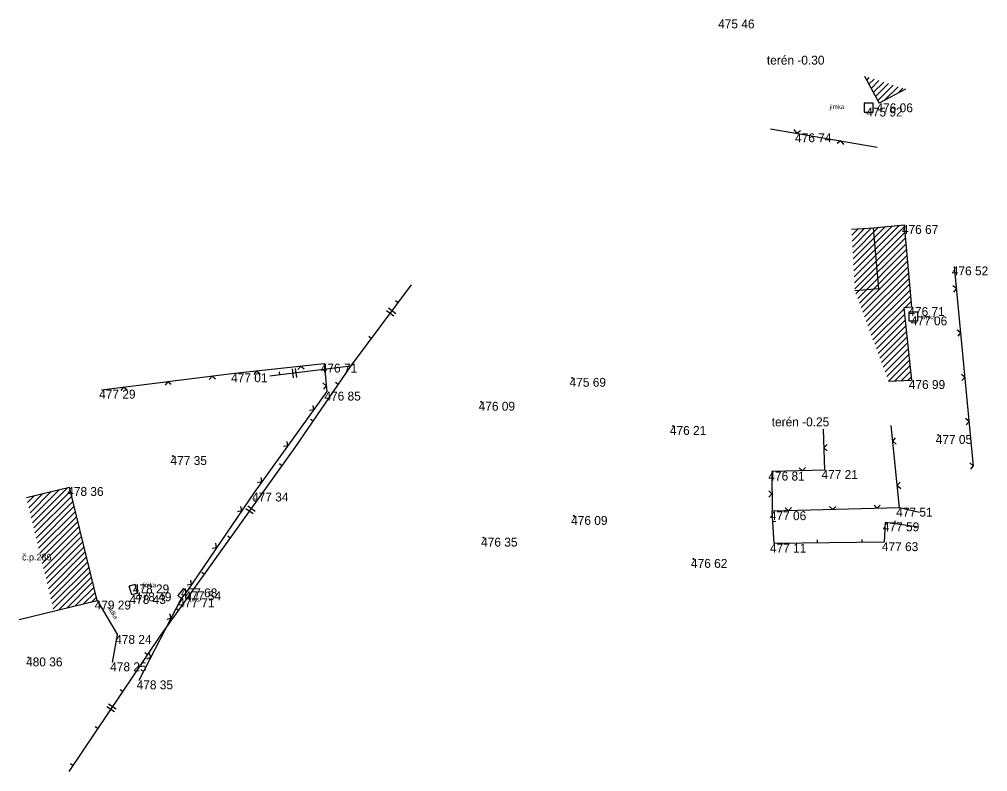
# Model space of a CAD drawing. Extents: x -553731 to -553573, y -1076100 to -1075378.
# Drawn here: x -553694.9 to -553586.1, y -1076100.4 to -1076015.8 of the extents above; entities that cross this region are included whole.
import ezdxf

# ---------------------------------------------------------------- set-up
doc = ezdxf.new("R2010")
doc.units = 0
for name, color, linetype in [('1', 7, 'Continuous'), ('12', 7, 'Continuous'), ('14', 7, 'Continuous'), ('18', 7, 'Continuous'), ('32', 7, 'Continuous'), ('50', 7, 'Continuous'), ('52', 7, 'Continuous'), ('54', 7, 'Continuous'), ('6', 7, 'Continuous'), ('62', 7, 'Continuous')]:
    doc.layers.add(name, color=color, linetype=linetype)

# ---------------------------------------------------------------- blocks, each defined once
blk = doc.blocks.new('POINT_DISPLAY')
blk.add_line((0, 0), (0, 0))
blk = doc.blocks.new('T')
at = {"layer": '6'}
blk.add_circle((0, 0), 0.05, dxfattribs=at)
blk = doc.blocks.new('SA')
at = {"layer": '50'}
blk.add_lwpolyline([(-0.5, -0.5), (0.5, -0.5), (0.5, 0.5), (-0.5, 0.5)], close=True, dxfattribs=at)
blk = doc.blocks.new('ROV')
at = {"layer": '62'}
for p, q in [((-0.348, -0.51), (-0.348, 0.51)), ((0, -0.51), (0, 0.51))]:
    blk.add_line(p, q, dxfattribs=at)

msp = doc.modelspace()

# ---------------------------------------------------------------- linework, layer by layer
at = {"layer": '12'}
for p, q in [((-553610.46, -1076028.1), (-553598.51, -1076030.16)), ((-553607.51, -1076028.61), (-553607.8, -1076028.2)), ((-553607.51, -1076028.61), (-553607.1, -1076028.32)), ((-553602.58, -1076029.46), (-553602.99, -1076029.75)), ((-553602.58, -1076029.46), (-553602.29, -1076029.87)), ((-553589.83, -1076043.58), (-553587.69, -1076066.04)), ((-553589.59, -1076046.07), (-553589.98, -1076045.75)), ((-553589.59, -1076046.07), (-553589.91, -1076046.46)), ((-553589.12, -1076051.05), (-553589.51, -1076050.73)), ((-553589.12, -1076051.05), (-553589.44, -1076051.43)), ((-553670.71, -1076055.59), (-553660.63, -1076054.5)), ((-553663.25, -1076054.78), (-553663.57, -1076055.17)), ((-553663.25, -1076054.78), (-553662.86, -1076055.1)), ((-553660.63, -1076054.5), (-553660.33, -1076057.65)), ((-553685.64, -1076057.43), (-553670.71, -1076055.59)), ((-553673.23, -1076055.9), (-553673.54, -1076056.3)), ((-553673.23, -1076055.9), (-553672.84, -1076056.21)), ((-553668.22, -1076055.32), (-553668.54, -1076055.71)), ((-553668.22, -1076055.32), (-553667.83, -1076055.64)), ((-553588.64, -1076056.02), (-553589.03, -1076055.71)), ((-553588.64, -1076056.02), (-553588.96, -1076056.41)), ((-553683.16, -1076057.12), (-553683.47, -1076057.52)), ((-553683.16, -1076057.12), (-553682.76, -1076057.43)), ((-553678.2, -1076056.51), (-553678.5, -1076056.91)), ((-553678.2, -1076056.51), (-553677.8, -1076056.82)), ((-553660.39, -1076056.99), (-553660.78, -1076056.67)), ((-553660.39, -1076056.99), (-553660.71, -1076057.38)), ((-553660.33, -1076057.65), (-553668.48, -1076068.99)), ((-553661.79, -1076059.68), (-553661.87, -1076059.19)), ((-553661.79, -1076059.68), (-553662.28, -1076059.76)), ((-553588.17, -1076061), (-553588.56, -1076060.68)), ((-553595.98, -1076070.69), (-553596.92, -1076061.46)), ((-553588.17, -1076061), (-553588.49, -1076061.39)), ((-553604.38, -1076066.47), (-553604.54, -1076061.86)), ((-553596.74, -1076063.23), (-553596.42, -1076062.84)), ((-553664.71, -1076063.74), (-553665.2, -1076063.82)), ((-553664.71, -1076063.74), (-553664.79, -1076063.25)), ((-553604.47, -1076063.97), (-553604.12, -1076063.6)), ((-553596.74, -1076063.23), (-553596.35, -1076063.55)), ((-553604.47, -1076063.97), (-553604.1, -1076064.31)), ((-553587.7, -1076065.98), (-553588.08, -1076065.66)), ((-553587.7, -1076065.98), (-553588.02, -1076066.36)), ((-553604.38, -1076066.47), (-553610.34, -1076066.64)), ((-553610.34, -1076066.64), (-553610.28, -1076071.09)), ((-553606.88, -1076066.54), (-553607.24, -1076066.2)), ((-553606.88, -1076066.54), (-553606.54, -1076066.18)), ((-553667.62, -1076067.8), (-553668.12, -1076067.88)), ((-553667.62, -1076067.8), (-553667.71, -1076067.31)), ((-553596.23, -1076068.2), (-553595.92, -1076067.81)), ((-553596.23, -1076068.2), (-553595.84, -1076068.52)), ((-553668.48, -1076068.99), (-553676.05, -1076080.09)), ((-553610.31, -1076069.14), (-553610.67, -1076068.79)), ((-553610.31, -1076069.14), (-553610.66, -1076069.5)), ((-553598.48, -1076070.76), (-553598.84, -1076070.42)), ((-553598.48, -1076070.76), (-553598.14, -1076070.4)), ((-553669.89, -1076071.06), (-553670.38, -1076071.15)), ((-553669.89, -1076071.06), (-553669.98, -1076070.56)), ((-553595.98, -1076070.69), (-553610.28, -1076071.09)), ((-553610.07, -1076074.73), (-553610.28, -1076071.09)), ((-553608.47, -1076071.04), (-553608.84, -1076070.7)), ((-553608.47, -1076071.04), (-553608.13, -1076070.68)), ((-553603.48, -1076070.9), (-553603.84, -1076070.56)), ((-553603.48, -1076070.9), (-553603.13, -1076070.54)), ((-553593.72, -1076071.23), (-553595.98, -1076070.69)), ((-553610.21, -1076072.23), (-553609.86, -1076072.21)), ((-553597.58, -1076072.34), (-553597.69, -1076074.57)), ((-553594.05, -1076072.85), (-553597.58, -1076072.34)), ((-553596.52, -1076072.49), (-553596.47, -1076072.15)), ((-553672.71, -1076075.19), (-553672.8, -1076074.69)), ((-553597.69, -1076074.57), (-553610.07, -1076074.73)), ((-553605.19, -1076074.67), (-553605.19, -1076074.32)), ((-553600.19, -1076074.6), (-553600.19, -1076074.25)), ((-553672.71, -1076075.19), (-553673.2, -1076075.28)), ((-553675.52, -1076079.32), (-553675.62, -1076078.82)), ((-553675.52, -1076079.32), (-553676.02, -1076079.41)), ((-553676.68, -1076080.88), (-553681.44, -1076090.1)), ((-553677.83, -1076083.1), (-553678.3, -1076083.25)), ((-553677.83, -1076083.1), (-553677.98, -1076082.62)), ((-553680.12, -1076087.54), (-553680.6, -1076087.7)), ((-553680.12, -1076087.54), (-553680.27, -1076087.07))]:
    msp.add_line(p, q, dxfattribs=at)
at = {"layer": '14'}
for p, q in [((-553599.92, -1076022.19), (-553598.28, -1076025.25)), ((-553595.29, -1076023.65), (-553598.28, -1076025.25)), ((-553598.92, -1076039.23), (-553595.43, -1076038.92)), ((-553594.61, -1076048.15), (-553595.43, -1076038.92)), ((-553601.38, -1076039.39), (-553598.92, -1076039.23)), ((-553598.31, -1076046.09), (-553598.92, -1076039.23)), ((-553598.31, -1076046.09), (-553601, -1076046.33)), ((-553594.61, -1076048.15), (-553595.48, -1076048.24)), ((-553595.48, -1076048.24), (-553594.64, -1076056.35)), ((-553597.22, -1076056.47), (-553594.64, -1076056.35)), ((-553694.09, -1076069.55), (-553689.23, -1076068.37)), ((-553686.14, -1076081.13), (-553689.23, -1076068.37)), ((-553694.88, -1076083.25), (-553686.14, -1076081.13))]:
    msp.add_line(p, q, dxfattribs=at)
at = {"layer": '18'}
for p, q in [((-553681.86, -1076079.32), (-553682.52, -1076079.51)), ((-553682.25, -1076080.5), (-553682.52, -1076079.51)), ((-553681.59, -1076080.31), (-553681.86, -1076079.32)), ((-553676.45, -1076079.76), (-553677.08, -1076080.55)), ((-553676.05, -1076080.09), (-553676.68, -1076080.88)), ((-553676.45, -1076079.76), (-553676.05, -1076080.09)), ((-553686.14, -1076081.13), (-553683.86, -1076084.99)), ((-553681.59, -1076080.31), (-553682.25, -1076080.5)), ((-553677.08, -1076080.55), (-553676.68, -1076080.88)), ((-553684.41, -1076088.07), (-553683.86, -1076084.99))]:
    msp.add_line(p, q, dxfattribs=at)
at = {"layer": '32'}
for p, q in [((-553599.67, -1076022.66), (-553599.38, -1076022.36)), ((-553599.42, -1076023.11), (-553598.84, -1076022.53)), ((-553599.18, -1076023.58), (-553598.3, -1076022.7)), ((-553598.93, -1076024.04), (-553597.76, -1076022.87)), ((-553598.68, -1076024.5), (-553597.23, -1076023.04)), ((-553598.44, -1076024.96), (-553596.69, -1076023.21)), ((-553597.72, -1076024.95), (-553596.15, -1076023.38)), ((-553596.2, -1076024.14), (-553595.61, -1076023.55)), ((-553601.34, -1076040.06), (-553600.62, -1076039.34)), ((-553601.31, -1076040.73), (-553599.86, -1076039.29)), ((-553601.27, -1076041.4), (-553599.11, -1076039.24)), ((-553601.23, -1076042.07), (-553598.34, -1076039.18)), ((-553601.2, -1076042.74), (-553597.56, -1076039.11)), ((-553601.16, -1076043.41), (-553596.79, -1076039.04)), ((-553601.12, -1076044.08), (-553596.01, -1076038.97)), ((-553601.09, -1076044.76), (-553595.42, -1076039.08)), ((-553601.05, -1076045.43), (-553595.36, -1076039.73)), ((-553601.01, -1076046.1), (-553595.3, -1076040.38)), ((-553600.88, -1076046.67), (-553595.24, -1076041.03)), ((-553600.68, -1076047.18), (-553595.19, -1076041.68)), ((-553600.49, -1076047.7), (-553595.13, -1076042.33)), ((-553600.3, -1076048.21), (-553595.07, -1076042.98)), ((-553600.11, -1076048.73), (-553595.01, -1076043.63)), ((-553599.92, -1076049.24), (-553594.95, -1076044.28)), ((-553599.72, -1076049.76), (-553594.9, -1076044.93)), ((-553599.53, -1076050.27), (-553594.84, -1076045.58)), ((-553599.34, -1076050.79), (-553594.78, -1076046.23)), ((-553599.15, -1076051.3), (-553594.72, -1076046.88)), ((-553595.37, -1076048.23), (-553594.67, -1076047.53)), ((-553598.96, -1076051.82), (-553595.47, -1076048.33)), ((-553598.77, -1076052.33), (-553595.41, -1076048.97)), ((-553598.57, -1076052.85), (-553595.34, -1076049.61)), ((-553598.38, -1076053.36), (-553595.27, -1076050.26)), ((-553598.19, -1076053.88), (-553595.21, -1076050.9)), ((-553598, -1076054.39), (-553595.14, -1076051.54)), ((-553597.81, -1076054.91), (-553595.07, -1076052.18)), ((-553597.61, -1076055.43), (-553595.01, -1076052.82)), ((-553597.42, -1076055.94), (-553594.94, -1076053.46)), ((-553597.23, -1076056.46), (-553594.87, -1076054.1)), ((-553596.5, -1076056.44), (-553594.81, -1076054.74)), ((-553595.76, -1076056.4), (-553594.74, -1076055.38)), ((-553595.02, -1076056.37), (-553594.67, -1076056.02)), ((-553693.95, -1076070.12), (-553693.16, -1076069.32)), ((-553693.81, -1076070.69), (-553692.22, -1076069.09)), ((-553693.68, -1076071.26), (-553691.29, -1076068.87)), ((-553693.54, -1076071.82), (-553690.36, -1076068.64)), ((-553693.4, -1076072.39), (-553689.43, -1076068.42)), ((-553693.26, -1076072.96), (-553689.12, -1076068.82)), ((-553693.12, -1076073.53), (-553688.98, -1076069.39)), ((-553692.99, -1076074.1), (-553688.84, -1076069.96)), ((-553692.85, -1076074.67), (-553688.71, -1076070.53)), ((-553692.71, -1076075.24), (-553688.57, -1076071.1)), ((-553692.57, -1076075.81), (-553688.43, -1076071.67)), ((-553692.44, -1076076.38), (-553688.29, -1076072.24)), ((-553692.3, -1076076.95), (-553688.16, -1076072.81)), ((-553692.16, -1076077.52), (-553688.02, -1076073.38)), ((-553692.02, -1076078.09), (-553687.88, -1076073.94)), ((-553691.88, -1076078.66), (-553687.74, -1076074.51)), ((-553691.75, -1076079.22), (-553687.6, -1076075.08)), ((-553691.61, -1076079.79), (-553687.47, -1076075.65)), ((-553691.47, -1076080.36), (-553687.33, -1076076.22)), ((-553691.33, -1076080.93), (-553687.19, -1076076.79)), ((-553691.2, -1076081.5), (-553687.05, -1076077.36)), ((-553691.06, -1076082.07), (-553686.92, -1076077.93)), ((-553690.45, -1076082.18), (-553686.78, -1076078.5)), ((-553689.52, -1076081.95), (-553686.64, -1076079.07)), ((-553688.59, -1076081.72), (-553686.5, -1076079.64)), ((-553687.66, -1076081.5), (-553686.36, -1076080.21)), ((-553686.72, -1076081.27), (-553686.23, -1076080.78))]:
    msp.add_line(p, q, dxfattribs=at)
at = {"layer": '62'}
for p, q in [((-553650.84, -1076045.65), (-553657.65, -1076054.77)), ((-553652.34, -1076047.65), (-553652.62, -1076047.44)), ((-553655.33, -1076051.66), (-553655.61, -1076051.45)), ((-553657.65, -1076054.77), (-553666.73, -1076055.91)), ((-553657.65, -1076054.77), (-553663.91, -1076063.94)), ((-553660.63, -1076055.14), (-553660.58, -1076055.49)), ((-553665.59, -1076055.77), (-553665.63, -1076055.42)), ((-553659.06, -1076056.83), (-553659.35, -1076056.64)), ((-553661.88, -1076060.96), (-553662.17, -1076060.77)), ((-553663.91, -1076063.94), (-553679.09, -1076085.13)), ((-553665.37, -1076065.97), (-553665.65, -1076065.77)), ((-553668.28, -1076070.04), (-553668.56, -1076069.83)), ((-553671.19, -1076074.1), (-553671.47, -1076073.9)), ((-553674.1, -1076078.17), (-553674.39, -1076077.96)), ((-553677.01, -1076082.23), (-553677.3, -1076082.03)), ((-553679.09, -1076085.13), (-553689.31, -1076100.35)), ((-553680.48, -1076087.21), (-553680.77, -1076087.01)), ((-553683.27, -1076091.36), (-553683.56, -1076091.16)), ((-553686.06, -1076095.51), (-553686.35, -1076095.31)), ((-553688.85, -1076099.66), (-553689.14, -1076099.46))]:
    msp.add_line(p, q, dxfattribs=at)

# ---------------------------------------------------------------- block references
at = {"layer": '1'}
for p in [(-553616.1, -1076015.83), (-553599.45, -1076025.73), (-553598.28, -1076025.25), (-553607.46, -1076028.62), (-553595.43, -1076038.92), (-553589.83, -1076043.58), (-553594.61, -1076048.15), (-553594.44, -1076049.2), (-553660.63, -1076054.5), (-553670.71, -1076055.59), (-553632.77, -1076056.1), (-553594.64, -1076056.35), (-553685.64, -1076057.43), (-553660.33, -1076057.65), (-553642.98, -1076058.79), (-553621.4, -1076061.51), (-553591.65, -1076062.52), (-553677.63, -1076064.89), (-553610.34, -1076066.64), (-553604.38, -1076066.47), (-553689.23, -1076068.37), (-553668.48, -1076068.99), (-553610.28, -1076071.09), (-553595.98, -1076070.69), (-553632.59, -1076071.62), (-553597.58, -1076072.34), (-553642.72, -1076074.06), (-553610.07, -1076074.73), (-553597.69, -1076074.57), (-553619.13, -1076076.45), (-553681.86, -1076079.32), (-553681.62, -1076080.21), (-553676.45, -1076079.76), (-553676.05, -1076080.09), (-553686.14, -1076081.13), (-553682.25, -1076080.5), (-553676.68, -1076080.88), (-553683.86, -1076084.99), (-553693.84, -1076087.52), (-553684.41, -1076088.07), (-553681.44, -1076090.1)]:
    msp.add_blockref('POINT_DISPLAY', p, dxfattribs=at)
at = {"layer": '32'}
for p in [(-553599.92, -1076022.19), (-553601.38, -1076039.39), (-553694.09, -1076069.55)]:
    msp.add_blockref('POINT_DISPLAY', p, dxfattribs=at)
at = {"layer": '50'}
for p in [(-553599.45, -1076025.73), (-553594.44, -1076049.2)]:
    msp.add_blockref('SA', p, dxfattribs=at)
at = {"layer": '6'}
for p in [(-553632.77, -1076056.1), (-553642.98, -1076058.79), (-553621.4, -1076061.51), (-553591.65, -1076062.52), (-553677.63, -1076064.89), (-553632.59, -1076071.62), (-553642.72, -1076074.06), (-553619.13, -1076076.45), (-553693.84, -1076087.52)]:
    msp.add_blockref('T', p, dxfattribs=at)
at = {"layer": '62'}
for p, xscale, yscale, rotation in [((-553653.21, -1076048.83), 1.0000003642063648, 1.000000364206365, -126.74898170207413), ((-553664.16, -1076055.59), 0.999999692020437, 0.999999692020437, -172.8478804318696), ((-553669.01, -1076071.06), 0.9999997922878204, 0.9999997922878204, -125.61682918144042), ((-553684.42, -1076093.06), 1.0000017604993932, 1.0000017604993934, 56.11923880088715)]:
    msp.add_blockref('ROV', p, dxfattribs=dict(at, xscale=xscale, yscale=yscale, rotation=rotation))

# ---------------------------------------------------------------- texts
at = {"layer": '52'}
for s, p in [('jímka', (-553603.84, -1076025.88)), ('jímka', (-553593.57, -1076049.53)), ('jímka', (-553681.15, -1076079.63)), ('pris', (-553675.72, -1076081.26))]:
    msp.add_text(s, height=0.5, dxfattribs=at).set_placement(p)
msp.add_text('zídka', height=0.5, rotation=300.5692, dxfattribs=at).set_placement((-553685.02, -1076081.86))
at = {"layer": '54'}
msp.add_text('č.p.286', height=0.75, dxfattribs=at).set_placement((-553694.57, -1076076.62))
at = {"layer": '6'}
for s, p in [('475 46 ', (-553616.36, -1076016.83)), ('terén -0.30', (-553610.88, -1076020.9)), ('475 92 ', (-553599.72, -1076026.73)), ('476 06 ', (-553598.57, -1076026.25)), ('476 74 ', (-553607.72, -1076029.62)), ('476 67 ', (-553595.71, -1076039.92)), ('476 52 ', (-553590.1, -1076044.58)), ('476 71 ', (-553594.99, -1076049.15)), ('477 06 ', (-553594.71, -1076050.2)), ('476 71 ', (-553661.01, -1076055.5)), ('477 01 ', (-553671.08, -1076056.59)), ('475 69 ', (-553633.05, -1076057.1)), ('476 99 ', (-553594.94, -1076057.35)), ('477 29 ', (-553685.91, -1076058.43)), ('476 85 ', (-553660.6, -1076058.65)), ('476 09 ', (-553643.27, -1076059.79)), ('terén -0.25', (-553610.34, -1076061.55)), ('476 21 ', (-553621.78, -1076062.51)), ('477 05 ', (-553591.91, -1076063.52)), ('477 35 ', (-553677.89, -1076065.89)), ('476 81 ', (-553610.72, -1076067.64)), ('477 21 ', (-553604.75, -1076067.47)), ('478 36 ', (-553689.5, -1076069.37)), ('477 34 ', (-553668.73, -1076069.99)), ('477 06 ', (-553610.55, -1076072.09)), ('477 51 ', (-553596.35, -1076071.69)), ('476 09 ', (-553632.88, -1076072.62)), ('477 59 ', (-553597.85, -1076073.34)), ('476 35 ', (-553642.99, -1076075.06)), ('477 11 ', (-553610.54, -1076075.73)), ('477 63 ', (-553597.96, -1076075.57)), ('476 62 ', (-553619.41, -1076077.45)), ('478 29 ', (-553682.13, -1076080.32)), ('478 49 ', (-553681.88, -1076081.21)), ('477 68 ', (-553676.72, -1076080.76)), ('477 54 ', (-553676.3, -1076081.09)), ('479 29 ', (-553686.42, -1076082.13)), ('478 43 ', (-553682.5, -1076081.5)), ('477 71 ', (-553677.04, -1076081.88)), ('478 24 ', (-553684.11, -1076085.99)), ('480 36 ', (-553694.12, -1076088.52)), ('478 25 ', (-553684.67, -1076089.07)), ('478 35 ', (-553681.7, -1076091.1))]:
    msp.add_text(s, height=1, dxfattribs=at).set_placement(p)

doc.saveas('drawing.dxf')
